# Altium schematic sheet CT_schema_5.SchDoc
size 371 x 336 mm
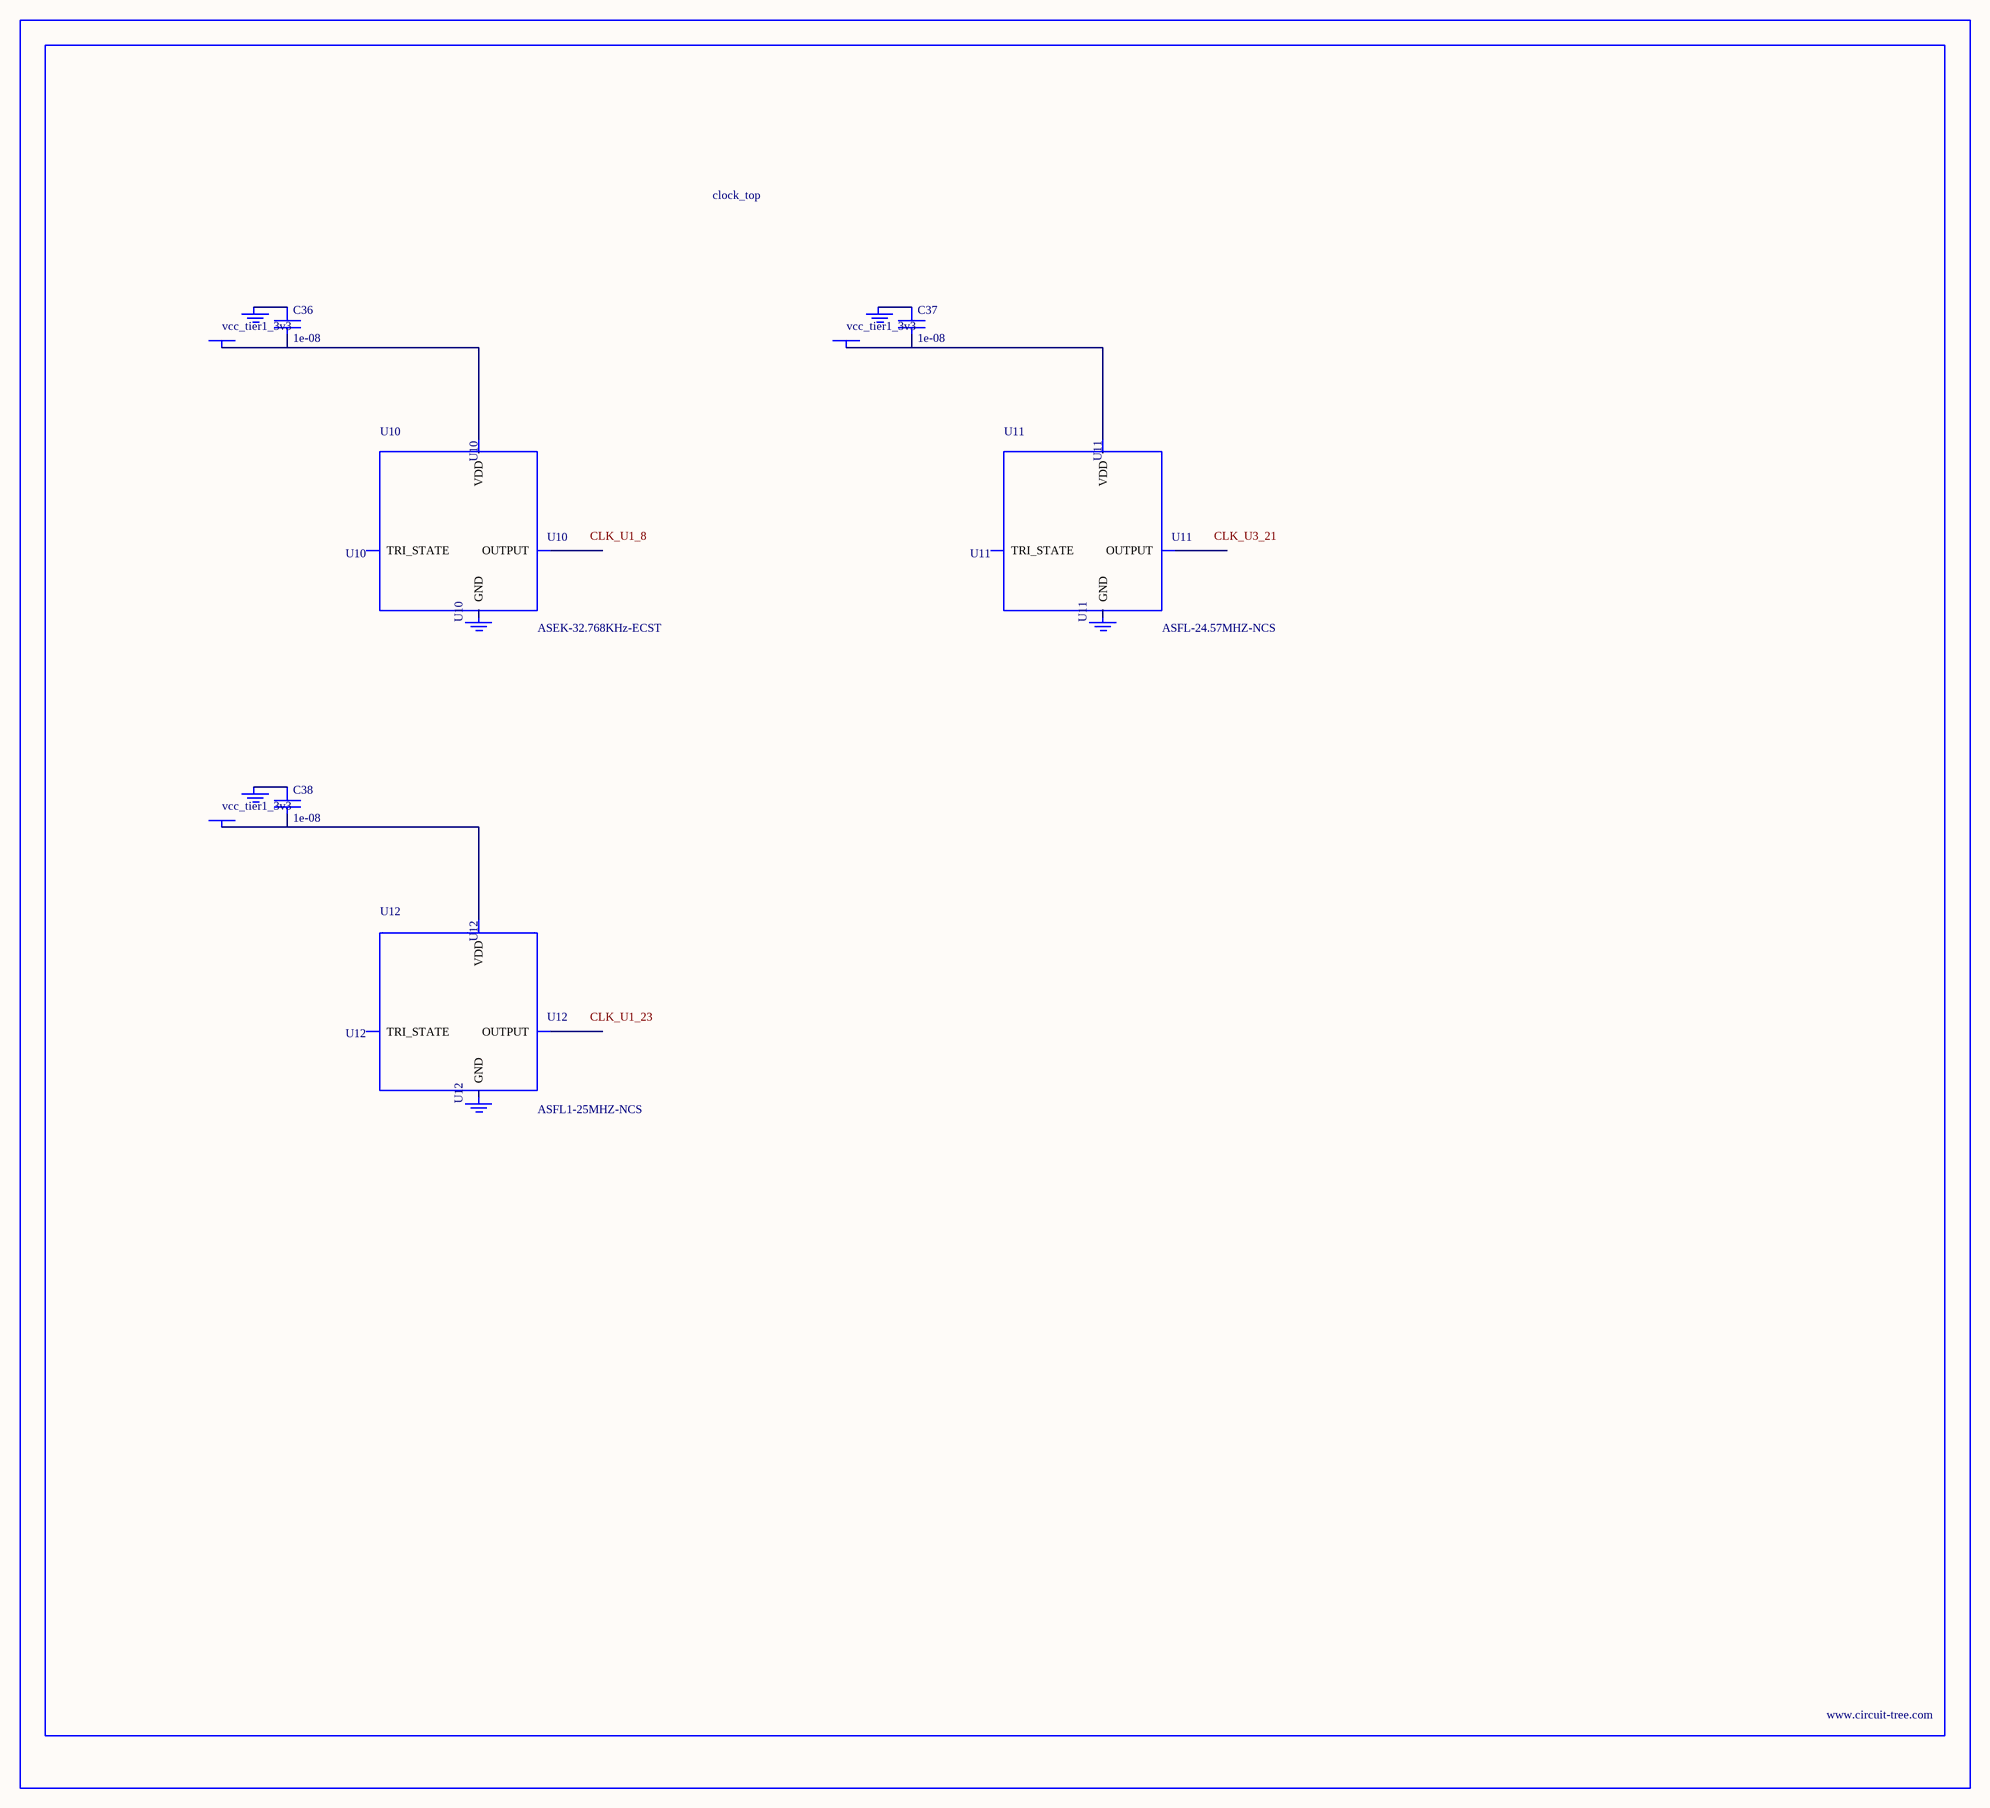
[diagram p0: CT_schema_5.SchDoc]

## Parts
BORDER4  (no value)
C36  1e-08  [C0402]
C37  1e-08  [C0402]
C38  1e-08  [C0402]
GND_INSTANCE_4_0  (no value)
GND_INSTANCE_4_1  (no value)
GND_INSTANCE_4_2  (no value)
GND_INSTANCE_4_3  (no value)
GND_INSTANCE_4_4  (no value)
GND_INSTANCE_4_5  (no value)
POWER_INSTANCE_4_0  vcc_tier1_3v3
POWER_INSTANCE_4_1  vcc_tier1_3v3
POWER_INSTANCE_4_2  vcc_tier1_3v3
U10  ASEK-32.768KHz-ECST  [ASEK]
U11  ASFL-24.57MHZ-NCS  [ASFL1]
U12  ASFL1-25MHZ-NCS  [ASFL1]

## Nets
NetC36_1: C36.1 GND_INSTANCE_4_0.0(GND)
NetC36_2: C36.2 POWER_INSTANCE_4_0.0(PWR) U10.4(VDD)
NetC37_1: C37.1 GND_INSTANCE_4_2.0(GND)
NetC37_2: C37.2 POWER_INSTANCE_4_1.0(PWR) U11.4(VDD)
NetC38_1: C38.1 GND_INSTANCE_4_4.0(GND)
NetC38_2: C38.2 POWER_INSTANCE_4_2.0(PWR) U12.4(VDD)

Not connected (* = marked no-connect by the designer): GND_INSTANCE_4_1 0(GND); GND_INSTANCE_4_3 0(GND); GND_INSTANCE_4_5 0(GND); U10 1(TRI_STATE) 2(GND) 3(OUTPUT); U11 1(TRI_STATE) 2(GND) 3(OUTPUT); U12 1(TRI_STATE) 2(GND) 3(OUTPUT)

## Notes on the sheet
- Labels drawn without touching a wire or pin: CLK_U1_8, CLK_U1_23, CLK_U3_21

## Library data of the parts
BORDER4 = BORDER_PAGE4
C36-C38 = C0402C103K3RAC
GND_INSTANCE_4_0-GND_INSTANCE_4_5 = GND
POWER_INSTANCE_4_0-POWER_INSTANCE_4_2 = PWR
